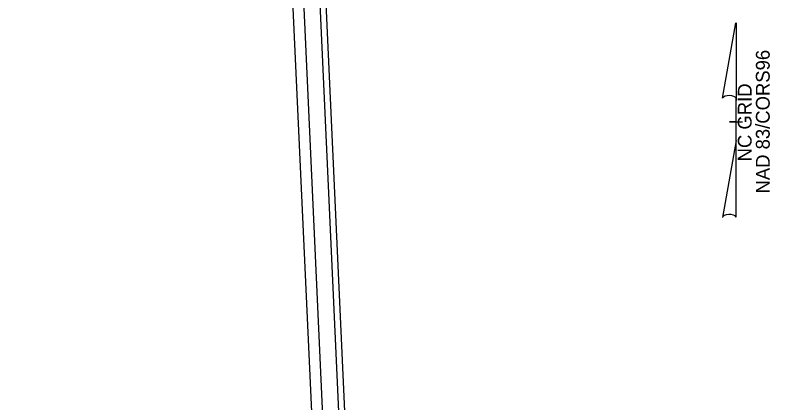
# Model space of a CAD drawing. Extents: x 1191070 to 1191932, y 892813 to 893283.
# Drawn here: x 1191699.2 to 1191931.5, y 893048.3 to 893167.7 of the extents above; entities that cross this region are included whole.
import ezdxf

# ---------------------------------------------------------------- set-up
doc = ezdxf.new("R2010")
doc.units = 0
for name, color, linetype in [('Prop North Arrow NAD83 for Plan Sheets CELL', 7, 'Continuous'), ('Sheet Border Standard 30in CELL', 7, 'Continuous'), ('Sheet Clip Boundary CELL', 7, 'Continuous'), ('Sheet Plot Border Inside CELL', 7, 'Continuous'), ('Sheet Plot Border Outside CELL', 7, 'Continuous')]:
    doc.layers.add(name, color=color, linetype=linetype)

msp = doc.modelspace()

# ---------------------------------------------------------------- linework, layer by layer
at = {"layer": 'Prop North Arrow NAD83 for Plan Sheets CELL'}
for p, q in [((1191917, 893142.19), (1191921.1, 893165.37)), ((1191921.12, 893165.37), (1191921.12, 893141.47)), ((1191921.12, 893129.07), (1191921.12, 893142.17)), ((1191921.12, 893141.47), (1191921.12, 893142.14)), ((1191920.9, 893134.87), (1191919.12, 893134.87)), ((1191919.15, 893134.87), (1191923.15, 893134.87)), ((1191921.12, 893129.07), (1191916.95, 893105.44)), ((1191921.15, 893105.54), (1191921.12, 893129.07))]:
    msp.add_line(p, q, dxfattribs=at)
for centre, start_param, end_param in [((1191919.07, 893141.95), 0.216388, 2.908219), ((1191919.07, 893105.36), 0.201328, 3.141593)]:
    msp.add_ellipse(centre, major_axis=(2.11, -0.02), ratio=0.461098, start_param=start_param, end_param=end_param, dxfattribs=at)
at = {"layer": 'Sheet Border Standard 30in CELL'}
msp.add_lwpolyline([(1191783.48, 893273.17), (1191184.11, 893245.75), (1191203.31, 892826.19), (1191802.68, 892853.61)], close=True, dxfattribs=at)
at = {"layer": 'Sheet Clip Boundary CELL'}
msp.add_lwpolyline([(1191201.31, 892936.07), (1191187.08, 893244.15), (1191703.39, 893267.99), (1191706.1, 893208.66), (1191782.81, 893212.17), (1191794.3, 892963.46), (1191451.08, 892947.61)], close=True, dxfattribs=at)
at = {"layer": 'Sheet Plot Border Inside CELL'}
msp.add_lwpolyline([(1191788.43, 893274.42), (1191122.53, 893243.95), (1191141.82, 892822.35), (1191807.72, 892852.82)], close=True, dxfattribs=at)
at = {"layer": 'Sheet Plot Border Outside CELL'}
msp.add_lwpolyline([(1191789.82, 893283.47), (1191116.92, 893252.68), (1191137.03, 892813.14), (1191809.93, 892843.93)], close=True, dxfattribs=at)

# ---------------------------------------------------------------- texts
at = {"layer": 'Prop North Arrow NAD83 for Plan Sheets CELL'}
for s, p in [('NAD 83/CORS96', (1191931.49, 893112.79)), ('NC GRID', (1191925.92, 893122.68))]:
    msp.add_text(s, height=4.25, rotation=90, dxfattribs=at).set_placement(p)

doc.saveas('drawing.dxf')
